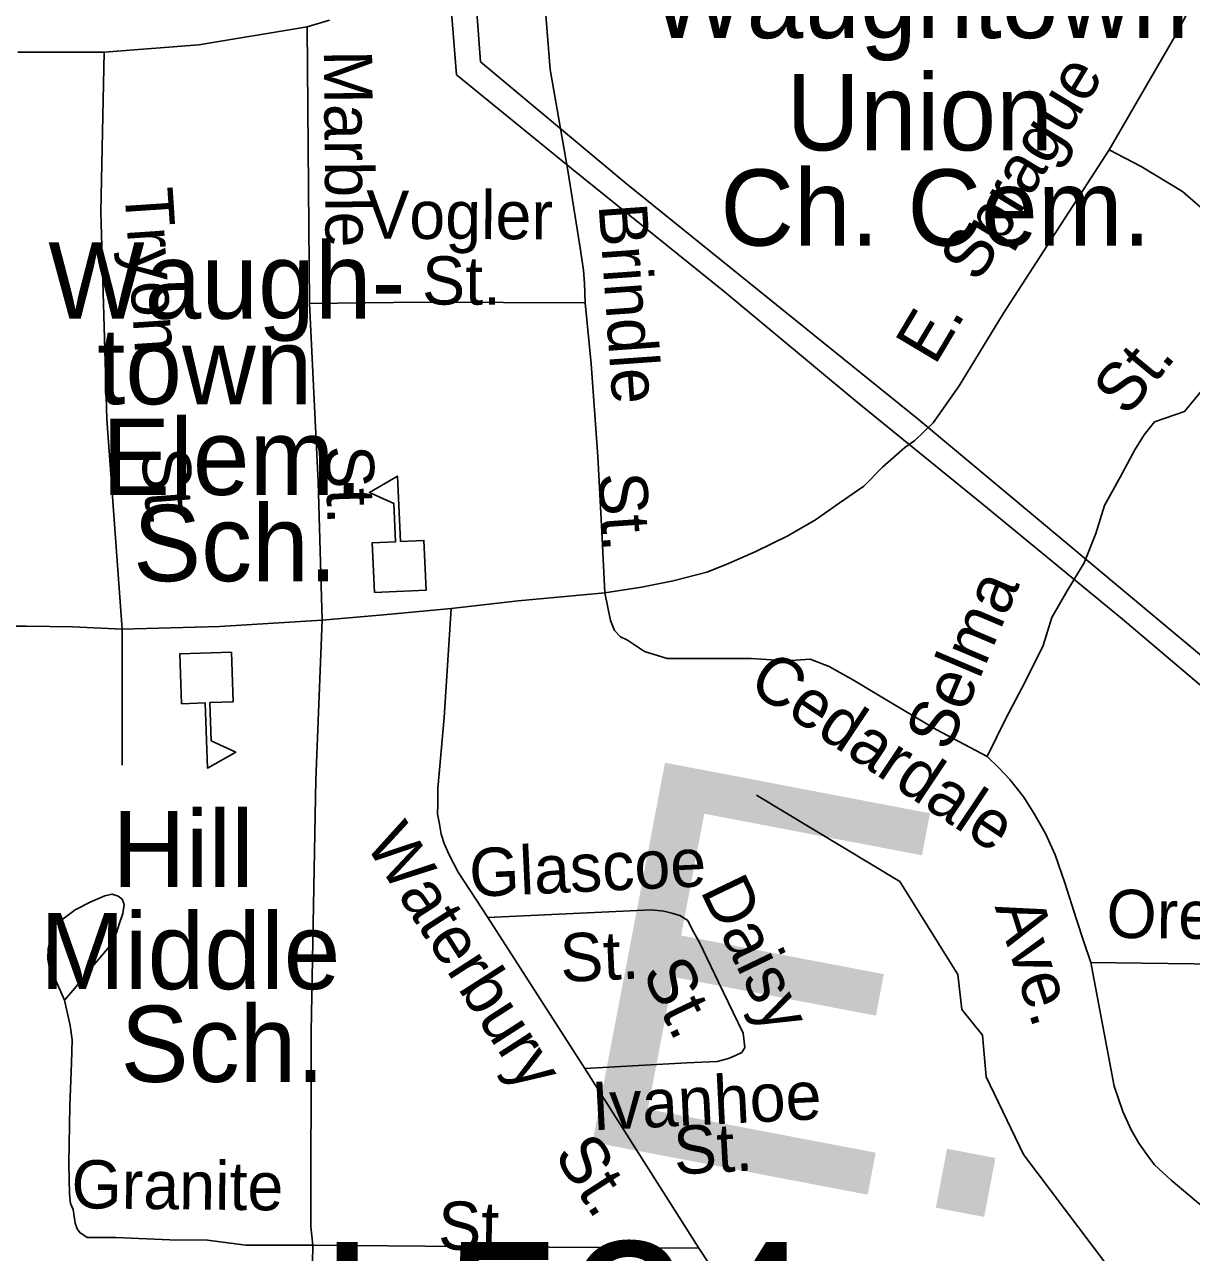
# Model space of a CAD drawing. Extents: x 1553981 to 1780076, y 812965 to 996873.
# Drawn here: x 1634902.9 to 1635189.7, y 846599.4 to 846901.4 of the extents above; entities that cross this region are included whole.
import ezdxf

# ---------------------------------------------------------------- set-up
doc = ezdxf.new("R2010")
doc.units = 0
for name, color, linetype in [('Exist Aviation Coast Guard Station CELL', 7, 'Continuous'), ('Exist Aviation Field Marked Auxiliary CELL', 7, 'Continuous'), ('Exist Cultural Educational Facility High Label', 7, 'Continuous'), ('Exist Hydrographic Misc Water Feature', 7, 'Continuous'), ('Exist Road Non-System Type 51 Label', 7, 'Continuous'), ('Exist Road Primary Interstate Structure Cantilever Sign Number Label', 7, 'Continuous'), ('Exist Road Secondary Type 51 Attributed', 7, 'Continuous'), ('Exist Utilities Electrical Transmission Line', 7, 'Continuous'), ('Map Preparation Border County Name Lower Right Label', 7, 'Continuous')]:
    doc.layers.add(name, color=color, linetype=linetype)

msp = doc.modelspace()

# ---------------------------------------------------------------- linework, layer by layer
at = {"layer": 'Exist Aviation Coast Guard Station CELL'}
for points in [[(1634988.87, 846761.7), (1634988.31, 846773.92), (1634994.06, 846774.18), (1634993.63, 846783.56), (1634987.62, 846786.32), (1634994.53, 846790.29), (1634995.26, 846774.24), (1635001.01, 846774.5), (1635001.56, 846762.27)], [(1634953.7, 846747.06), (1634954.16, 846734.83), (1634948.41, 846734.62), (1634948.76, 846725.24), (1634954.75, 846722.43), (1634947.81, 846718.52), (1634947.21, 846734.57), (1634941.46, 846734.36), (1634941, 846746.59)]]:
    msp.add_lwpolyline(points, close=True, dxfattribs=at)
at = {"layer": 'Exist Hydrographic Misc Water Feature'}
msp.add_lwpolyline([(1635273.05, 846521.7), (1635246.36, 846531.67), (1635175.11, 846588.11), (1635148.36, 846623.53), (1635139.24, 846642.58), (1635138.35, 846652.87), (1635133.24, 846659.13), (1635132.24, 846667.76), (1635117.99, 846690.62), (1635082.73, 846711.85)], dxfattribs=at)
at = {"layer": 'Exist Road Secondary Type 51 Attributed'}
msp.add_lwpolyline([(1634901.24, 846894.57), (1634922.44, 846894.57), (1634945.68, 846896.36), (1634972.28, 846900.79), (1634977.82, 846902.43)], dxfattribs=at)
at = {"layer": 'Exist Utilities Electrical Transmission Line'}
for points in [[(1634869.75, 847052.33), (1634976.64, 847010.96), (1635001.55, 847004.37), (1635004.29, 846965.6), (1635007.01, 846923.32), (1635007.56, 846907.55), (1635009.06, 846889.03), (1635037.26, 846865.92), (1635074.84, 846835.69), (1635107.48, 846808.52), (1635138.14, 846783.61), (1635172.75, 846755.16), (1635226.87, 846709.21), (1635247.38, 846691.96), (1635266.9, 846675.21)], [(1636375.85, 846890.8), (1636346.1, 846889.49), (1636261.6, 846885.32), (1636202.07, 846881.86), (1636143.83, 846878.86), (1636073.32, 846874.27), (1635989.55, 846870.34), (1635919.82, 846867.25), (1635837.31, 846863.83), (1635766.81, 846860.73), (1635738.73, 846851.35), (1635627.77, 846812.03), (1635508.32, 846769.31), (1635424.73, 846738.89), (1635323.32, 846702.95), (1635267.09, 846683.16), (1635250.28, 846696.63), (1635201.6, 846738.27), (1635122.5, 846804.31), (1635050.76, 846862.25), (1635014.93, 846892.22), (1635012.58, 846924.48)]]:
    msp.add_lwpolyline(points, dxfattribs=at)
at = {"layer": 'Map Preparation Border County Name Lower Right Label'}
for p, q in [((1635169.46, 846870.59), (1635143.48, 846830.35)), ((1634926.86, 846752.65), (1634926.86, 846719.21)), ((1635016.71, 846681.82), (1635040.59, 846644.69)), ((1635225.9, 846669.96), (1635164.91, 846670.68)), ((1635040.59, 846644.69), (1635068.61, 846600.5)), ((1634973.24, 846605.76), (1634973.67, 846601.25)), ((1634973.67, 846601.25), (1634973.32, 846578.77))]:
    msp.add_line(p, q, dxfattribs=at)
for points in [[(1635199.85, 846925.29), (1635185.57, 846898.44), (1635169.46, 846870.59)], [(1635029.53, 846922.32), (1635032.07, 846890.32), (1635036.42, 846865.49), (1635039.37, 846846.95), (1635040.28, 846840.95), (1635040.46, 846837.69), (1635040.64, 846832.94)], [(1634972.28, 846900.79), (1634972.65, 846861.28), (1634972.92, 846832.76)], [(1634922.44, 846894.57), (1634921.58, 846855.34), (1634923.09, 846804.28), (1634926.86, 846752.65)], [(1635169.46, 846870.59), (1635177.3, 846866.47), (1635187.45, 846860.31), (1635191.89, 846856.45)], [(1635040.64, 846832.94), (1635000.42, 846833.08), (1634972.92, 846832.76)], [(1634972.92, 846832.76), (1634975.04, 846788.92), (1634976.01, 846754.9)], [(1635040.64, 846832.94), (1635042.16, 846817.9), (1635043.77, 846795.13), (1635044.72, 846776.62), (1635045.49, 846761.6)], [(1635143.48, 846830.35), (1635132.57, 846812.53), (1635126.18, 846803.46), (1635121.65, 846799.09), (1635119.22, 846797.33), (1635113.71, 846792.51), (1635109.13, 846787.82), (1635103.07, 846783.69), (1635097.26, 846779.53), (1635090.43, 846775.65), (1635082.62, 846771.75), (1635075.33, 846768.62), (1635070.56, 846766.69), (1635062.26, 846764.59), (1635054.5, 846762.97), (1635045.49, 846761.6)], [(1635196.12, 846816.05), (1635187.97, 846806.19), (1635180.59, 846803.68), (1635178.05, 846800.48), (1635175.73, 846796.78), (1635172.14, 846790.07), (1635168.31, 846783.09), (1635166.21, 846776.21), (1635163.3, 846769), (1635159.15, 846762.07), (1635155.33, 846755.57), (1635153.23, 846748.7), (1635148.83, 846739.71), (1635144.06, 846730.73), (1635139.48, 846721.37)], [(1635045.49, 846761.6), (1635024.18, 846759.61), (1635007.72, 846757.78)], [(1635139.48, 846721.37), (1635126.9, 846728.05), (1635116, 846734.48), (1635106.61, 846740.12), (1635100.65, 846743.47), (1635095.94, 846745.29), (1635090.21, 846744.87), (1635081.42, 846745.45), (1635060.8, 846745.45), (1635055.26, 846747.17), (1635051.03, 846750.01), (1635049.3, 846750.79), (1635047.83, 846752.32), (1635046.88, 846754.84), (1635045.49, 846761.6)], [(1635007.72, 846757.78), (1634992, 846756.31), (1634976.01, 846754.9)], [(1635007.72, 846757.78), (1635006, 846730.99), (1635004.47, 846713.51), (1635004.41, 846709.51), (1635004.37, 846707.26), (1635004.84, 846704.75), (1635005.29, 846702.26), (1635006.02, 846699.99), (1635007.21, 846697.22), (1635009.4, 846692.92), (1635016.71, 846681.82)], [(1634926.86, 846752.65), (1634914.69, 846753.23), (1634903.3, 846753.43), (1634892.52, 846753.43), (1634881.51, 846753.43)], [(1634976.01, 846754.9), (1634950.76, 846753.35), (1634926.86, 846752.65)], [(1634976.01, 846754.9), (1634974.46, 846715.66), (1634973.29, 846653.76), (1634973.24, 846605.76)], [(1635139.48, 846721.37), (1635142.37, 846718.56), (1635145.07, 846715.7), (1635148.49, 846711.35), (1635151.15, 846707.05), (1635153.78, 846702.46), (1635156.17, 846697.2), (1635158.58, 846690.31), (1635161.45, 846681.25), (1635163.21, 846675.78), (1635164.91, 846670.68)], [(1634912.69, 846661.49), (1634910.51, 846666.27), (1634909.06, 846668.8), (1634908.59, 846671.56), (1634908.64, 846674.06), (1634909.2, 846676.8), (1634909.71, 846678.79), (1634910.23, 846679.78), (1634912.02, 846681.24), (1634915.29, 846683.7), (1634919.16, 846685.63), (1634922.59, 846687.08), (1634924.35, 846687.55), (1634925.84, 846687.02), (1634926.82, 846686.27), (1634927.3, 846685.01), (1634927.03, 846682.76), (1634926.18, 846680.38), (1634925.46, 846678.02), (1634923.64, 846674.55), (1634919.05, 846669.14), (1634915.23, 846664.44), (1634912.69, 846661.49)], [(1635016.71, 846681.82), (1635056.97, 846683.68), (1635059.96, 846683.37), (1635061.95, 846682.85), (1635063.94, 846682.31), (1635065.92, 846681.02), (1635066.88, 846679.02), (1635068.83, 846675.48), (1635073.41, 846665.91), (1635079.46, 846653.3), (1635079.92, 846649.82), (1635079.14, 846648.56), (1635077.62, 846647.84), (1635075.86, 846647.12), (1635073.09, 846646.4), (1635065.61, 846646.03), (1635040.59, 846644.69)], [(1635164.91, 846670.68), (1635170.7, 846640.34), (1635172.82, 846634.1), (1635174.83, 846629.53), (1635176.71, 846626.26), (1635178.68, 846623.47), (1635180.63, 846620.93), (1635184.73, 846617.17), (1635197.13, 846606.69), (1635216.85, 846590.1), (1635235.85, 846574.81), (1635240.52, 846570.74), (1635243.25, 846568.68), (1635246.46, 846566.39), (1635249.42, 846564.58), (1635254.54, 846559.62), (1635262.23, 846553.32), (1635270.27, 846546.67), (1635283.96, 846537.29), (1635290.69, 846531.44), (1635294.8, 846527.86), (1635302.37, 846521.91), (1635310.9, 846514.99)], [(1634912.69, 846661.49), (1634914.09, 846655.21), (1634914.52, 846651.7), (1634914.42, 846645.95), (1634914.01, 846635.45), (1634913.77, 846621.22), (1634913.92, 846613.72), (1634914.12, 846611.46), (1634914.84, 846609.95), (1634915.28, 846606.64), (1634915.8, 846605.21), (1634916.41, 846604.29), (1634918.25, 846603.06), (1634925.31, 846603.06), (1634938.6, 846602.54), (1634947.83, 846602.4), (1634957.24, 846601.22), (1634973.67, 846601.25)], [(1635068.61, 846600.5), (1635019.64, 846600.76), (1634973.67, 846601.25)], [(1635081.77, 846580.02), (1635079.09, 846584.57), (1635068.61, 846600.5)]]:
    msp.add_lwpolyline(points, dxfattribs=at)

# ---------------------------------------------------------------- texts
at = {"layer": 'Exist Aviation Field Marked Auxiliary CELL'}
for s, p in [('Waughtown', (1635056.65, 846898.02)), ('Union', (1635090.1, 846870.41)), ('Ch. Cem.', (1635073.87, 846846.99))]:
    msp.add_text(s, height=18.75, dxfattribs=at).set_placement(p)
at = {"layer": 'Exist Cultural Educational Facility High Label'}
for s, p in [('Waugh-', (1634908.69, 846829.02)), ('town', (1634920.65, 846808)), ('Elem.', (1634921.91, 846785.69)), ('Sch.', (1634929.52, 846764.48)), ('Hill', (1634924.38, 846689.25)), ('Middle', (1634906.63, 846664.16)), ('Sch.', (1634926.46, 846641.35))]:
    msp.add_text(s, height=18.75, dxfattribs=at).set_placement(p)
at = {"layer": 'Exist Road Non-System Type 51 Label'}
for s, height, rotation, p in [('Marble', 11.875, 270.5413, (1634976.4, 846895.03)), ('Sprague', 11.875, 58.9336, (1635137.32, 846837.58)), ('Tryon', 11.875, 273.7664, (1634927.38, 846860.88)), ('Vogler', 11.875, 359.7979, (1634986.81, 846848.69)), ('Brindle', 11.875, 274.0539, (1635043.94, 846857.04)), ('St.', 11.875, 359.7979, (1635000.54, 846832.52)), ('E.', 11.875, 59.184, (1635126.61, 846817.29)), ('St.', 11.875, 50.4911, (1635173.78, 846804.63)), ('St.', 11.875, 274.1691, (1634931.53, 846796.94)), ('St.', 11.875, 271.8344, (1634976.74, 846797.74)), ('St.', 11.875, 274.0539, (1635043.84, 846790.88)), ('Selma', 11.875, 67.0361, (1635129.97, 846722.26)), ('Cedardale', 11.875, 326.2354, (1635080.26, 846738.13)), ('E.', 95, 349.1878, (1635032.22, 846628.49)), ('Waterbury', 11.875, 302.7513, (1634986.34, 846700)), ('Glascoe', 11.875, 2.6432, (1635012.42, 846686.82)), ('Daisy', 11.875, 295.6292, (1635068.82, 846688.4)), ('Oregon', 11.875, 359.312, (1635168.72, 846676.8)), ('Ave.', 11.875, 287.7586, (1635141.28, 846684.45)), ('St.', 11.875, 2.6432, (1635034.73, 846665.89)), ('St.', 11.875, 295.6292, (1635054.52, 846668.39)), ('Ivanhoe', 11.875, 2.8536, (1635042.53, 846629.44)), ('St.', 11.875, 3.0733, (1635062.69, 846618.55)), ('St.', 11.875, 302.7513, (1635032.76, 846623.49)), ('Granite', 11.875, 359.3973, (1634914.34, 846610.29)), ('St.', 11.875, 359.3973, (1635004.47, 846600.12))]:
    msp.add_text(s, height=height, rotation=rotation, dxfattribs=at).set_placement(p)
at = {"layer": 'Exist Road Primary Interstate Structure Cantilever Sign Number Label'}
msp.add_text('L524', height=41.01, dxfattribs=at).set_placement((1634975.08, 846560.99))

doc.saveas('drawing.dxf')
